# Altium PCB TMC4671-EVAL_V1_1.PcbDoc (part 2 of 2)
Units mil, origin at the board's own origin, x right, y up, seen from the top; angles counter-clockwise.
Board outline 2165.36 x 3346.46 mil, 6 copper layers (Top, GND1, MID, VM, GND2, Bottom), stack 61.733 mil thick; 157 components, 127 nets, 622 pads, 423 vias.
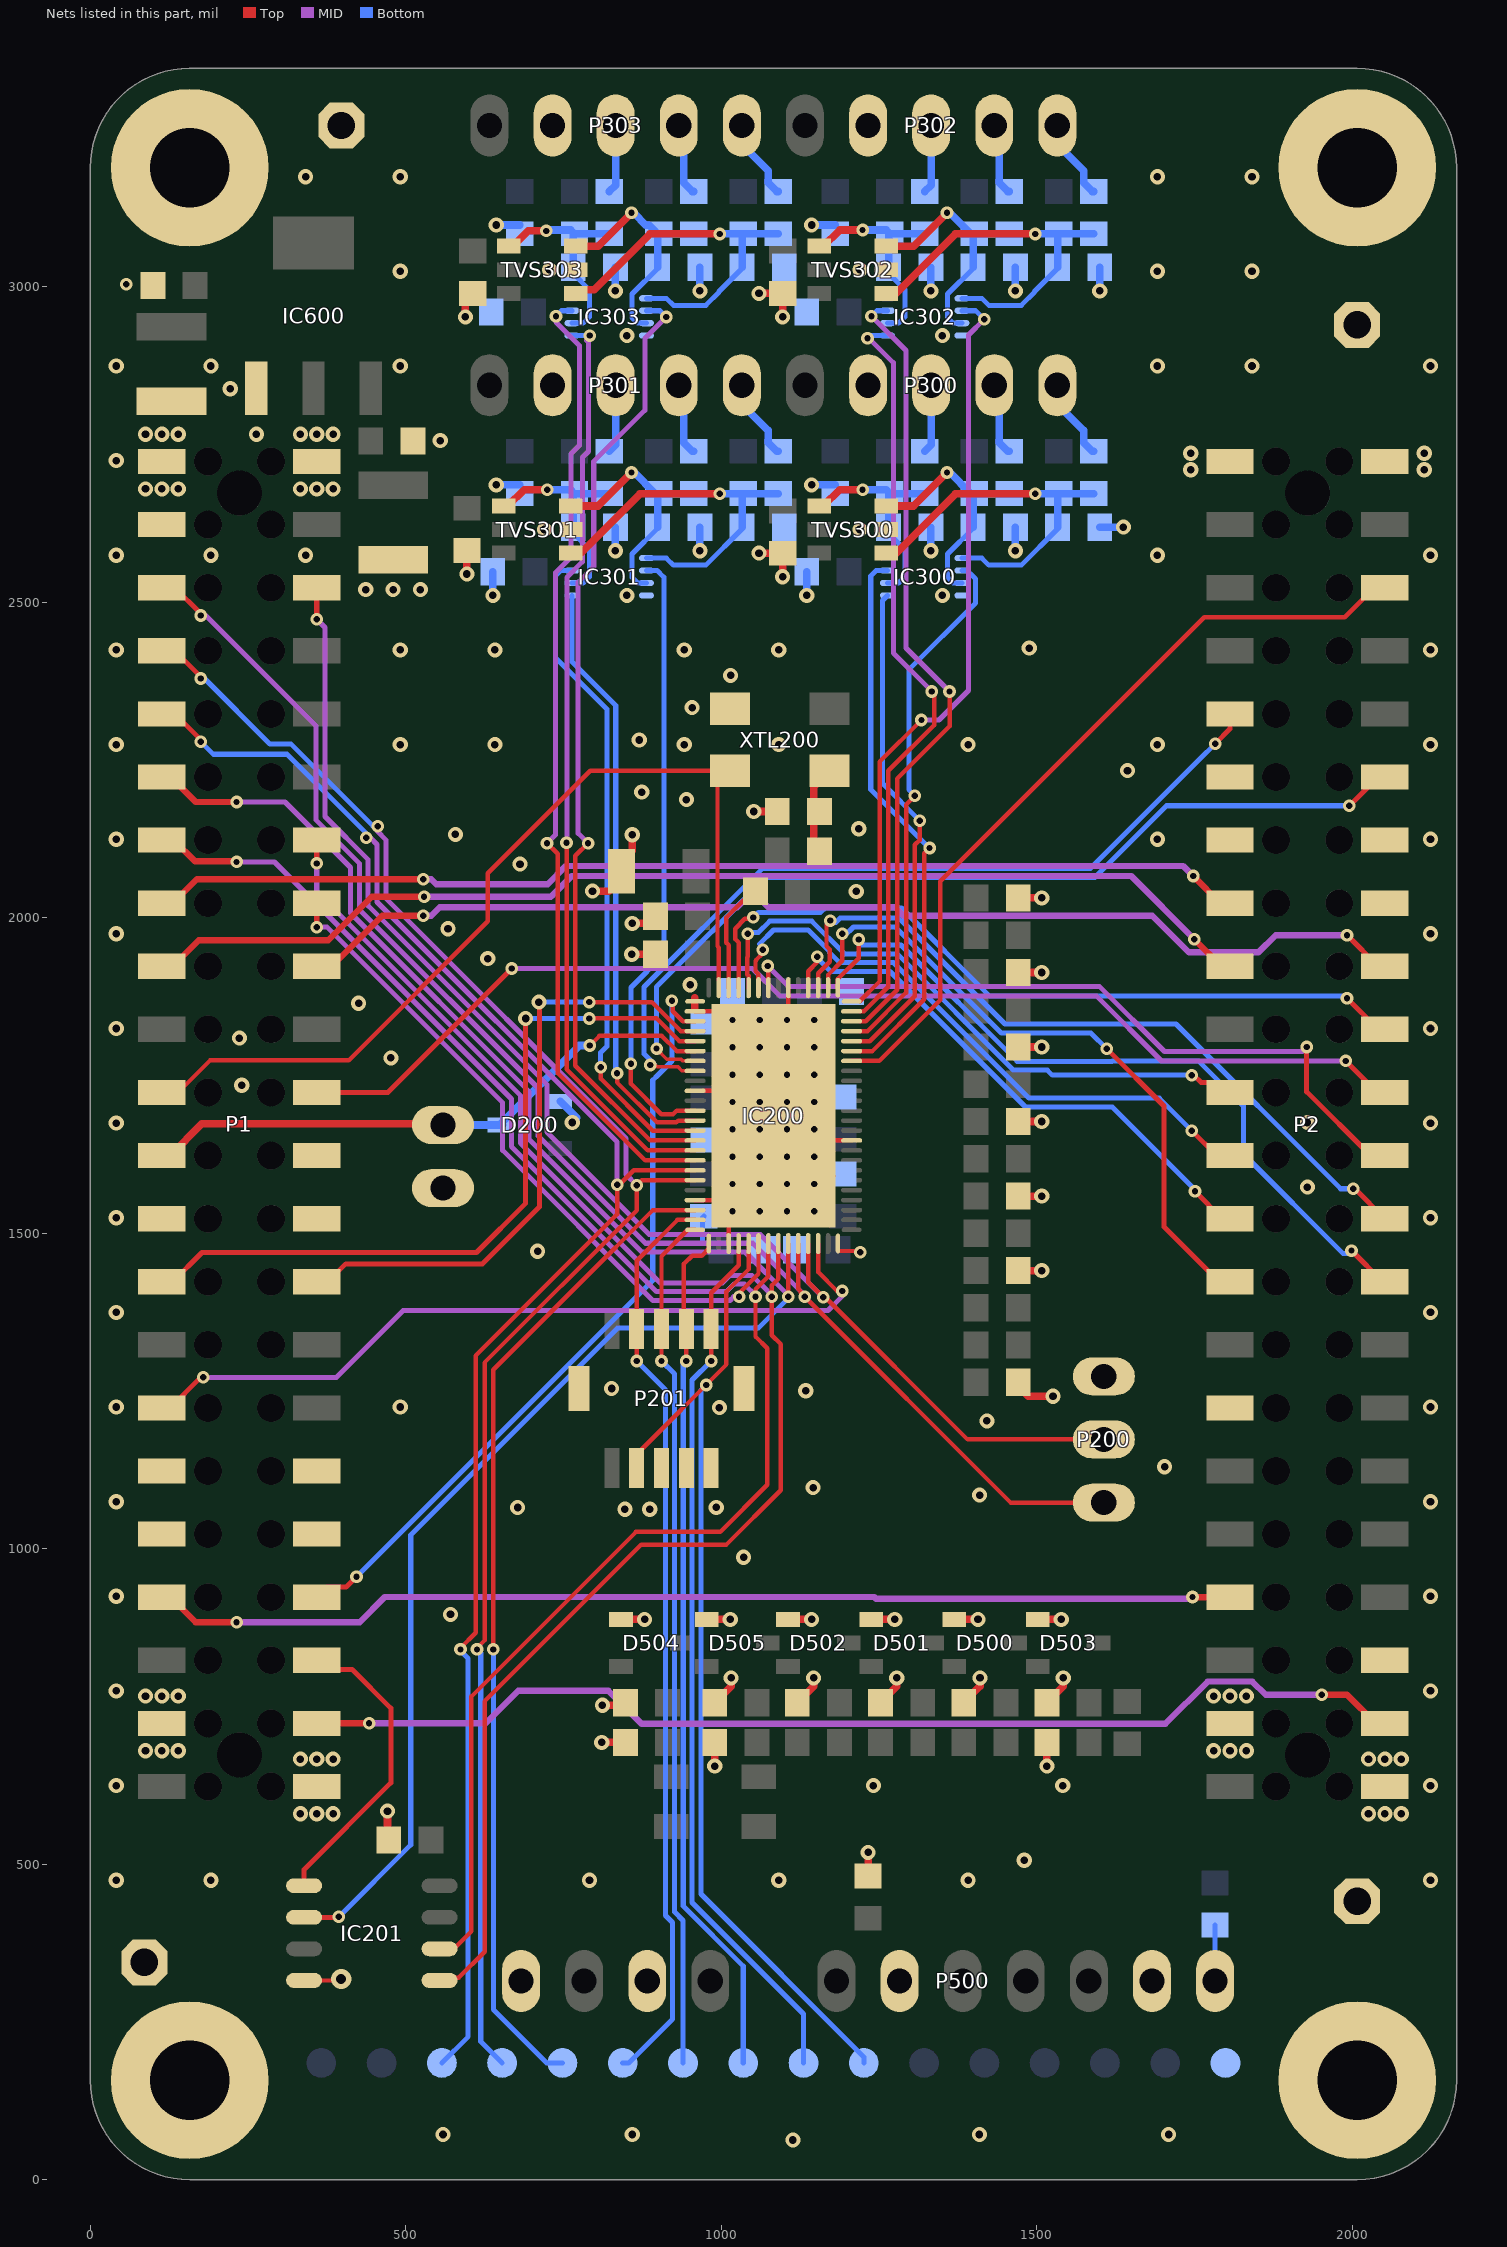
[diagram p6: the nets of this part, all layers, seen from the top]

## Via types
v1: diameter 24, hole 12, Top to Bottom, tented both sides, 171 vias
v2: diameter 20, hole 10, Top to Bottom, tented both sides, 136 vias
v3: diameter 24.1, hole 12, Top to Bottom, tented both sides, 67 vias
v4: diameter 24, hole 10, Top to Bottom, 32 vias
v5: diameter 26, hole 14, Top to Bottom, tented both sides, 7 vias
v6: diameter 32, hole 16, Top to Bottom, tented both sides, 6 vias
v7: diameter 39.37, hole 23.62, Top to Bottom, tented both sides, 2 vias
v8: diameter 50, hole 40, Top to Bottom, tented both sides, 2 vias

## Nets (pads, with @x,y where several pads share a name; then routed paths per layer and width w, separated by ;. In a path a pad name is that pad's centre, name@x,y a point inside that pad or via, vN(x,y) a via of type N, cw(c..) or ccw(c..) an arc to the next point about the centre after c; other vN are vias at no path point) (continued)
BRAKE_OUT: P400.2 R406.1 | length 88.6
  Bottom w8: P400.2@1782.68,314.96 R406.1@1782.68,403.6
CLK25: IC200.51 P1.23 XTL200.3 | length 1499.1
  Top w7.1: P1.23@113.5,1723.23 138.94,1723.23 189.73,1774.01 409.45,1774.01 629.92,1994.49 629.92,2070.52 792.53,2233.13 XTL200.3@986.5,2233.13 ; IC200.51@996.06,1901.99 996.06,1952.75 994.08,1954.74 994.08,2209.55 1001.53,2217 1002.62,2217 XTL200.3@986.5,2233.13 ; XTL200.3@1014.06,2233.13 XTL200.3@1013.82,2233.13 XTL200.3@986.5,2233.13
CS_CH0: IC201.1 P1.6 | length 487.1
  Top w8: IC201.1@339.01,465.94 339.01,491.76 476.38,629.13 476.38,747.24 414.97,808.65 373.52,808.65 P1.6@358.94,823.23
DBG_SPI_MISO: IC200.4 P201.9 TP9.1 | length 1402.5
  Top w7.1: v2(984.06,1297.62) P201.9@984.06,1348.47 984.06,1405.66 1027.56,1449.16 IC200.4@1027.56,1483.74
  Bottom w8: v2(984.06,1297.62) 953.76,1267.32 953.76,439.45 1130.45,262.77 TP9.1@1130.45,185.04
DBG_SPI_MOSI: IC200.1 P201.7 TP8.1 | length 1365.2
  Top w7.1: v2(944.69,1297.62) P201.7@944.69,1348.47 940.75,1352.41 940.75,1451.44 953.96,1464.65 969.38,1464.65 980.31,1475.59 IC200.1@980.31,1483.74
  Bottom w8: v2@939.76,1297.62 939.76,433.66 1034.91,338.51 TP8.1@1034.91,185.04
DBG_SPI_nSCS: IC200.75 P201.3 TP6.1 | length 1458.3
  Top w7.1: v2(865.95,1297.62) P201.3@865.95,1348.47 ; P201.3@869.95,1352.47 P201.3@865.95,1348.47 ; IC200.75@958.66,1521.15 930.55,1521.15 865.95,1456.55 P201.3@865.95,1348.47
  Bottom w8: TP6.1@843.83,185.04 853.26,185.04 922.68,254.45 922.68,407.79 911.76,418.71 911.76,1251.81 v2(865.95,1297.62)
DBG_SPI_SCK: IC200.76 P201.5 TP7.1 | length 1369
  Top w7.1: v2(905.32,1297.62) P201.5@905.32,1348.47 ; P201.5@909.32,1352.47 P201.5@905.32,1348.47 ; IC200.76@958.66,1505.4 947.13,1505.4 905.32,1463.59 P201.5@905.32,1348.47
  Bottom w8: v2(905.32,1297.62) 925.76,1277.18 925.76,424.5 939.37,410.9 TP7.1@939.37,185.04
DBG_SPI_TRG: IC200.5 P201.4 TP10.1 | length 1614.2
  Top w7.1: P201.4@865.95,1127.99 865.95,1149.73 1008.3,1292.08 1008.3,1407.73 1043.31,1442.74 IC200.5@1043.31,1483.74
  Bottom w8: v2(976.06,1259.65) 967.76,1251.36 967.76,452.71 1225.98,194.48 TP10.1@1225.98,185.04
DIO1: P1.9
DIO2: P1.10
DIO3: P1.11
DIO4: P1.12
DIO8: P1.19
DIO9: P1.20
DIO11: P1.22
DRV_ERROR: P2.13
EN_IN: IC200.55 P1.8 | length 1255.7
  Top w7.1: v2(921.85,1868.62) 923.12,1867.35 923.12,1851.98 938.99,1836.11 IC200.55@958.66,1836.11
  Top w8: P1.8@358.94,923.23 374.94,939.23 405.37,939.23 v2(421.85,955.7)
  Bottom w8: v2(421.85,955.7) 891.45,1425.31 891.45,1742.64 899.68,1750.87 921.85,1773.03 v2(921.85,1868.62)
EN_OUT: IC200.32 P2.40 | length 1266
  Top w7.1: IC200.32@1206.69,1773.11 1250.29,1773.11 1346.94,1869.76 1346.94,2057.76 1765.56,2476.38 1988.19,2476.38 2035.04,2523.23 P2.40@2051.85,2523.23
ENC1_A: IC200.35 IC300.2 | length 835.2
  Top w7.1: IC200.35@1219.43,1820.42 1231.82,1820.42 1292.94,1881.54 1292.94,2179.43 1306.85,2193.34 v2(1306.85,2193.62)
  Bottom w8: v2(1306.85,2193.62) 1297.3,2203.16 1297.3,2393.08 1403.31,2499.08 1403.31,2536.89 1394.57,2545.63 1393.65,2545.63 1388.88,2550.39 IC300.2@1381.5,2550.39
ENC1_A_5V: C308.2 IC300.6 R302.1 R312.1 TVS300.4 | length 355.3
  Top w12: TVS300.4@1155.12,2652.76 1162.01,2652.76 1187.59,2678.33 v2(1224.01,2678.33)
  Bottom w8: IC300.6@1263.39,2530.71 1281.1,2530.71 1290.94,2540.55 1290.94,2583.86 1265.35,2609.45 C308.2@1265.35,2619.29
  Bottom w12: v2(1224.01,2678.33) 1261.43,2678.33 R312.1@1267.32,2672.44 ; C308.2@1265.35,2619.29 1265.35,2670.47 R312.1@1267.32,2672.44 ; R302.1@1322.44,2672.44 R312.1@1267.32,2672.44
ENC1_A_IN: P300.3 R302.2 | length 109
  Bottom w12: R302.2@1322.44,2739.37 1332.68,2749.61 P300.3@1332.68,2844.09
ENC1_B: IC200.34 IC300.5 | length 783
  Top w7.1: IC200.34@1219.43,1804.61 1235.6,1804.61 1306.94,1875.95 1306.94,2115.7 1314.49,2123.25 v2(1314.49,2154.02)
  Bottom w8: IC300.5@1263.39,2511.02 1255.43,2503.07 1255.43,2213.08 v2(1314.49,2154.02)
ENC1_B_5V: C312.2 IC300.3 R301.1 R316.1 TVS300.3 | length 405.6
  Top w12: TVS300.3@1261.42,2652.76 1304.73,2652.76 v2(1357.87,2705.89)
  Bottom w8: IC300.3@1381.5,2530.71 1367.72,2530.71 1358.68,2539.74 1358.68,2576.8 C312.2@1399.21,2617.32
  Bottom w12: v2(1357.87,2705.89) 1361.8,2705.89 1395.26,2672.44 R316.1@1401.18,2672.44 ; C312.2@1399.21,2619.29 1399.21,2670.47 R316.1@1401.18,2672.44 ; R301.1@1456.3,2672.44 R316.1@1401.18,2672.44
ENC1_B_IN: P300.2 R301.2 | length 115.7
  Bottom w12: P300.2@1432.68,2844.09 1440.65,2836.13 1440.65,2753.06 1454.33,2739.37 R301.2@1456.3,2739.37
ENC1_N: IC200.33 IC300.7 | length 879.6
  Top w7.1: IC200.33@1219.43,1788.86 1239.65,1788.86 1321.85,1871.05 1321.85,2102.32 v2(1330.24,2110.72)
  Bottom w8: IC300.7@1263.39,2550.39 1245.67,2550.39 1236.98,2541.71 1236.98,2203.24 1329.51,2110.72 v2(1330.24,2110.72)
ENC1_N_5V: C316.2 IC300.1 R300.1 R320.1 TVS300.1 | length 604.3
  Top w12: TVS300.1@1261.42,2577.95 1277.17,2577.95 1371.31,2672.09 v2(1497.68,2672.09)
  Bottom w8: IC300.1@1381.5,2570.08 1413,2570.08 1424.18,2558.89 1475.67,2558.89 1533.07,2616.29 C316.2@1533.07,2619.29
  Bottom w12: v2(1497.68,2672.09) R320.1@1534.69,2672.09 ; C316.2@1533.07,2619.29 1533.07,2670.47 R320.1@1534.69,2672.09 ; R300.1@1590.16,2672.44 R320.1@1535.04,2672.44 R320.1@1534.69,2672.09
ENC1_N_IN: P300.1 R300.2 | length 129.7
  Bottom w12: P300.1@1532.68,2844.09 1532.68,2814.09 1574.41,2772.36 1574.41,2753.15 1588.19,2739.37 R300.2@1590.16,2739.37
ENC2_A: IC200.64 IC301.2 | length 980.4
  Top w7.1: v2(856.85,1768.62) 856.85,1736.98 905.06,1688.76 923.55,1688.76 929.16,1694.37 IC200.64@958.66,1694.37
  Bottom w8: v2(856.85,1768.62) 856.85,1889.52 908.98,1941.65 908.98,2539.85 898.43,2550.39 IC301.2@881.5,2550.39
ENC2_A_5V: C309.2 IC301.6 R305.1 R313.1 TVS301.4 | length 355.3
  Top w12: TVS301.4@655.12,2652.76 662.01,2652.76 687.59,2678.33 v2(724.01,2678.33)
  Bottom w8: IC301.6@763.39,2530.71 781.1,2530.71 790.94,2540.55 790.94,2583.86 765.35,2609.45 C309.2@765.35,2619.29
  Bottom w12: v2(724.01,2678.33) 761.43,2678.33 R313.1@767.32,2672.44 ; C309.2@765.35,2619.29 765.35,2670.47 R313.1@767.32,2672.44 ; R305.1@822.44,2672.44 R313.1@767.32,2672.44
ENC2_A_IN: P301.3 R305.2 | length 109
  Bottom w12: R305.2@822.44,2739.37 832.68,2749.61 P301.3@832.68,2844.09
ENC2_B: IC200.65 IC301.5 | length 952.8
  Top w7.1: v2(834.94,1753.76) 834.94,1739.08 898.36,1675.66 928.97,1675.66 931.93,1678.61 IC200.65@958.66,1678.63
  Bottom w8: IC301.5@763.39,2511.02 763.39,2405.88 832.85,2336.42 832.85,1755.85 v2(834.94,1753.76)
ENC2_B_5V: C313.2 IC301.3 R304.1 R317.1 TVS301.3 | length 405.6
  Top w12: TVS301.3@761.42,2652.76 804.73,2652.76 v2(857.87,2705.89)
  Bottom w8: IC301.3@881.5,2530.71 867.72,2530.71 858.68,2539.74 858.68,2576.8 C313.2@899.21,2617.32
  Bottom w12: v2(857.87,2705.89) 861.8,2705.89 895.26,2672.44 R317.1@901.18,2672.44 ; C313.2@899.21,2619.29 899.21,2670.47 R317.1@901.18,2672.44 ; R304.1@956.3,2672.44 R317.1@901.18,2672.44
ENC2_B_IN: P301.2 R304.2 | length 115.7
  Bottom w12: P301.2@932.68,2844.09 940.65,2836.13 940.65,2753.06 954.33,2739.37 R304.2@956.3,2739.37
ENC2_N: IC200.66 IC301.7 | length 1048.6
  Top w7.1: v2(808.94,1763.23) 808.94,1745.28 891.66,1662.56 934.4,1662.56 934.65,1662.82 IC200.66@958.66,1662.88 IC200.66@958.66,1662.88
  Bottom w8: IC301.7@763.39,2550.39 745.67,2550.39 736.98,2541.71 736.98,2412.48 818.85,2330.62 818.85,1796.34 808.94,1786.43 v2(808.94,1763.23)
ENC2_N_5V: C317.2 IC301.1 R303.1 R321.1 TVS301.1 | length 604.3
  Top w12: TVS301.1@761.42,2577.95 777.17,2577.95 871.31,2672.09 v2(997.68,2672.09)
  Bottom w8: IC301.1@881.5,2570.08 913,2570.08 924.18,2558.89 975.67,2558.89 1033.07,2616.29 C317.2@1033.07,2619.29
  Bottom w12: v2(997.68,2672.09) R321.1@1034.69,2672.09 ; C317.2@1033.07,2619.29 1033.07,2670.47 R321.1@1034.69,2672.09 ; R303.1@1090.16,2672.44 R321.1@1035.04,2672.44 R321.1@1034.69,2672.09
ENC2_N_IN: P301.1 R303.2 | length 129.7
  Bottom w12: P301.1@1032.68,2844.09 1032.68,2814.09 1074.41,2772.36 1074.41,2753.15 1088.19,2739.37 R303.2@1090.16,2739.37
EXT_REF: P2.6
GND: C200.2 C201.1 C300.1 C301.1 C302.1 C303.1 C304.2 C305.2 C306.2 C307.2 C308.1 C309.1 C310.1 C311.1 C312.1 C313.1 C314.1 C315.1 C316.1 C317.1 C318.1 C319.1 C320.1 C321.1 C322.1 C323.1 C500.1 C501.1 C502.1 C503.1 C504.1 C505.1 C506.1 C507.1 C508.1 C600.1 C601.1 C602.1 C603.1 C604.1 C605.1 C606.1 C607.1 C608.1 C609.1 C610.1 C611.1 C612.1 C613.1 C614.2 C615.1 D200.1 D500.1 D501.1 D502.1 D503.1 D504.1 D505.1 IC200.3 IC200.14 IC200.24 IC200.44 IC200.53 IC200.54 IC200.62 IC200.73 IC200.77 IC201.4 IC300.4 IC301.4 IC302.4 IC303.4 IC600.1 MNT1.1 MNT2.1 MNT3.1 MNT4.1 P1.2 P1.3 P1.43 P1.44 P2.2 P2.3 P2.43 P2.44 P200.1 P201.6 P201.8 P201.10 P201.11 P201.12 P202.2 P300.4 P301.4 P302.4 P303.4 P400.1 P500.4 P501.2 P502.2 PIN1.1 PIN2.1 PIN3.1 PIN4.1 R401.1 R403.1 R405.1 R408.1 R410.1 R507.2 R508.2 R509.2 TP14.1 TVS300.2 TVS301.2 TVS302.2 TVS303.2 XTL200.2 | length 3304.7
  Top w6: IC201.4@339.01,315.94 395.47,315.94 v6(397.64,318.11) ; IC200.77@988.25,1851.85 1082.68,1757.43 IC200.77@1082.68,1686.5 1122.05,1647.13 IC200.77@1178.1,1591.08 ; IC200.14@1185.04,1483.74 1185.04,1472.04 1220.57,1472.04 v2(1220.57,1470) v2@1220,1470
  Top w7.1: IC200.73@958.66,1552.64 IC200.77@988.25,1552.64 ; IC200.54@958.66,1851.85 IC200.77@988.25,1851.85 ; IC200.62@971.39,1725.87 IC200.77@1043.31,1725.87 ; IC200.3@1011.81,1483.74 IC200.77@1011.81,1615.63 ; IC200.77@1106.3,1710.12 IC200.44@1106.3,1889.26 ; IC200.77@1122.05,1647.13 IC200.24@1206.69,1647.13
  Top w8: IC200.77@988.25,1552.64 1011.81,1576.2 IC200.77@1011.81,1584.14 ; IC200.77@1011.81,1615.63 v4(1017.72,1621.54) v4(1061.02,1664.85) IC200.77@1082.68,1686.5 ; IC200.77@1043.31,1725.87 IC200.77@1082.68,1686.5 ; v4(1104.33,1708.15) IC200.77@1082.68,1686.5
  Top w11.81: IC200.54@957.8,1855.21 957.8,1873.2
  Top w12: v1(471.08,584.11) 471.08,540.32 C201.1@473.05,538.36 ; v1(594.49,2952.36) C307.2@594.49,2989.76 ; v1(596.94,2544.9) C305.2@596.94,2582.3 ; v1(795.95,2042.41) C612.1@821.5,2042.41 ; v1(810.63,693.04) R507.2@848.03,693.04 ; v1(811.7,751.97) 843.97,751.97 C506.1@848.03,756.03 ; D504.1@841.14,888.09 v1(878.54,888.09) ; v1(858.24,1942.37) C613.1@895.64,1942.37 ; v1(858.94,1991.23) 884.49,1991.23 C614.2@895.64,2002.37 ; C612.1@858.95,2106.06 v1(858.95,2131.61) ; D505.1@976.97,888.09 v1(1014.37,888.09) ; v1(989.76,655.64) R508.2@989.76,693.04 ; C507.1@989.76,756.03 1015.55,781.82 v1(1015.55,795.28) ; v1(1051.46,2168.52) C200.2@1088.86,2168.52 ; v1(1059.84,2577.95) C304.2@1097.24,2577.95 v1(1097.24,2540.55) ; v1(1059.84,2989.76) C306.2@1097.24,2989.76 v1(1097.24,2952.36) ; D502.1@1105.79,888.09 v1(1143.19,888.09) ; C505.1@1120.55,756.03 1146.34,781.82 v1(1146.34,795.28) ; C500.1@1232.68,481.42 v1(1232.68,518.83) ; D501.1@1237.68,888.09 v1(1275.08,888.09) ; C504.1@1252.44,756.03 1278.23,781.82 v1(1278.23,795.28) ; D500.1@1369.57,888.09 v1(1406.97,888.09) ; C503.1@1384.33,756.03 1410.12,781.82 v1(1410.12,795.28) ; C501.1@1470.63,1263.78 1467.47,1260.62 1486.47,1241.62 v1(1525.85,1241.62) ; R410.1@1470.63,1440.95 v1(1508.03,1440.95) ; C502.1@1470.63,1559.06 v1(1508.03,1559.06) ; R408.1@1470.63,1677.16 v1(1508.03,1677.16) ; R405.1@1470.63,1795.28 v1(1508.03,1795.28) ; R403.1@1470.63,1913.39 v1(1508.03,1913.39) ; R401.1@1470.63,2031.49 v1(1508.03,2031.49) ; D503.1@1501.46,888.09 v1(1538.86,888.09) ; v1(1516.22,655.64) R509.2@1516.22,693.04 ; C508.1@1516.22,756.03 1542.01,781.82 v1(1542.01,795.28)
  Bottom w8: 970,1485 970,1524.61 C610.1@972.44,1527.05
  Bottom w12: v1(637.99,2511.02) C321.1@637.99,2548.43 ; v1(643.31,2686.22) C301.1@680.71,2686.22 ; v1(643.31,3098.03) C303.1@680.71,3098.03 ; D200.1@745.08,1709.05 770.67,1683.46 763.78,1676.57 v1(763.78,1675.59) ; v1(832.28,2581.89) C309.1@832.28,2619.29 ; v1(832.28,2993.7) C311.1@832.28,3031.1 ; v1(966.14,2581.89) C313.1@966.14,2619.29 ; v1(966.14,2993.7) C315.1@966.14,3031.1 ; v1(1135.43,2511.02) C320.1@1135.43,2548.43 ; v1(1143.31,2686.22) C300.1@1180.71,2686.22 ; v1(1143.31,3098.03) C302.1@1180.71,3098.03 ; v1(1332.28,2581.89) C308.1@1332.28,2619.29 ; v1(1332.28,2993.7) C310.1@1332.28,3031.1 ; v1(1466.14,2581.89) C312.1@1466.14,2619.29 ; v1(1466.14,2993.7) C314.1@1466.14,3031.1 ; C316.1@1600,2619.29 v1(1637.4,2619.29) ; v1(1600,2993.7) C318.1@1600,3031.1
  other v1: 559.06,71.65 859.06,71.65 1409.06,71.65 1709.06,71.65 1480.31,506.3 332.96,579.92 358.94,579.92 384.92,579.92 2025.87,579.92 2051.85,579.92 2077.84,579.92 332.96,666.54 358.94,666.54 384.92,666.54 2025.87,666.54 2051.85,666.54 2077.84,666.54 87.52,679.92 113.5,679.92 139.48,679.92 1780.43,679.92 1806.41,679.92 1832.4,679.92 87.52,766.54 113.5,766.54 139.48,766.54 1780.43,766.54 1806.41,766.54 1832.4,766.54 570.87,896.06 1035.43,986.61 847.39,1062.62 886.76,1062.62 677.17,1065.35 992.06,1065.65 1409.45,1085.04 1145.67,1096.85 1421.06,1202.65 997.06,1223.65 1133.86,1250.39 826.23,1253.98 709.06,1471.65 1929.13,1573.23 1929.13,1675.59 240.16,1734.64 476.38,1777.95 236.22,1809.45 425.2,1864.57 950.63,1893.89 629.92,1935.43 566.93,1982.68 1213.94,2041.89 681.1,2085.04 578.74,2132.28 1217.94,2141.23 944.88,2187.4 874.02,2199.21 1643.94,2233.23 870.08,2281.89 953.94,2333.23 1014.94,2384.23 1488.19,2427.56 850.5,2510.96 1350.5,2510.96 436.54,2520.16 479.84,2520.16 523.15,2520.16 719.76,2615.42 1219.76,2615.42 87.52,2679.92 113.5,2679.92 139.48,2679.92 332.96,2679.92 358.94,2679.92 384.92,2679.92 1744.09,2710.24 2114.17,2710.24 1744.09,2736.22 2114.17,2736.22 554.65,2756.38 87.52,2766.54 113.5,2766.54 139.48,2766.54 263.31,2766.54 332.96,2766.54 358.94,2766.54 384.92,2766.54 221.85,2838.62 850.5,2922.77 1350.5,2922.77 727.63,3027.23 1219.76,3027.23
  other v2: 56.94,3004.23
  other v3: 1113.68,62.96 41.23,474.64 191.23,474.64 791.23,474.64 1091.23,474.64 1391.23,474.64 2124.12,474.64 41.23,624.64 1241.23,624.64 1541.23,624.64 2124.12,624.64 41.23,774.64 2124.12,774.64 41.23,924.64 2124.12,924.64 41.23,1074.64 2124.12,1074.64 1702.68,1129.96 41.23,1224.64 491.23,1224.64 2124.12,1224.64 41.23,1374.64 2124.12,1374.64 41.23,1524.64 2124.12,1524.64 41.23,1674.64 2124.12,1674.64 41.23,1824.64 2124.12,1824.64 41.23,1974.64 2124.12,1974.64 41.23,2124.64 1691.23,2124.64 2124.12,2124.64 41.23,2274.64 491.23,2274.64 641.23,2274.64 941.23,2274.64 1091.23,2274.64 1391.23,2274.64 1691.23,2274.64 2124.12,2274.64 41.23,2424.64 491.23,2424.64 641.23,2424.64 941.23,2424.64 1091.23,2424.64 2124.12,2424.64 41.23,2574.64 191.23,2574.64 341.23,2574.64 1691.23,2574.64 2124.12,2574.64 41.23,2724.64 41.23,2874.64 191.23,2874.64 491.23,2874.64 1691.23,2874.64 1841.23,2874.64 2124.12,2874.64 491.23,3024.64 1691.23,3024.64 1841.23,3024.64 341.23,3174.64 491.23,3174.64 1691.23,3174.64 1841.23,3174.64
  other v4: 1017.72,1534.93 1061.02,1534.93 1104.33,1534.93 1147.64,1534.93 1017.72,1578.23 1061.02,1578.23 1104.33,1578.23 1147.64,1578.23 1061.02,1621.54 1104.33,1621.54 1147.64,1621.54 1017.72,1664.85 1104.33,1664.85 1147.64,1664.85 1017.72,1708.15 1061.02,1708.15 1147.64,1708.15 1017.72,1751.46 1061.02,1751.46 1104.33,1751.46 1147.64,1751.46 1017.72,1794.77 1061.02,1794.77 1104.33,1794.77 1147.64,1794.77 1017.72,1838.08 1061.02,1838.08 1104.33,1838.08 1147.64,1838.08
GPIO0: IC200.70 P1.35 TP3.1 | length 2779.4
  Top w7.1: v2(586.85,840.46) 586.85,842.74 610.85,866.74 610.85,1306.26 835.07,1530.48 v2(835.07,1577.16) 838.59,1577.16 861.31,1599.89 IC200.70@958.66,1599.89
  Top w8: P1.35@113.5,2323.23 133.94,2323.23 174.94,2282.23 v2(174.94,2279.23)
  MID w8: v2(437.16,2126.76) 443.95,2126.76 454.5,2116.2 454.5,2025.1 835.07,1644.53 v2(835.07,1577.16)
  Bottom w8: v2(174.94,2279.23) 194.94,2259.23 311.76,2259.23 437.16,2133.83 v2(437.16,2126.76) ; TP3.1@557.22,185.04 598.85,226.67 598.85,826.11 ; v2(586.85,840.46) 586.85,838.17 598.85,826.17
GPIO1: IC200.71 P1.37 TP4.1 | length 2806.4
  Top w7.1: v2(612.85,840.46) 612.85,842.74 624.85,854.74 624.85,1295.13 865.94,1536.23 v2(865.94,1576.23) 873.85,1584.14 IC200.71@958.66,1584.14
  Top w8: P1.37@113.5,2423.23 133.94,2423.23 174.94,2382.23 v2(174.94,2379.23)
  MID w8: v2(455.54,2145.14) 455.54,2136.66 468.5,2123.7 468.5,2030.9 849.07,1650.33 849.07,1593.1 v2(865.94,1576.23)
  Bottom w8: v2(174.94,2379.23) 180.94,2379.23 284.94,2275.23 318.39,2275.23 448.47,2145.14 v2(455.54,2145.14) ; v2(612.85,840.46) 618.85,834.46 618.85,218.95 TP4.1@652.76,185.04
GPIO2: IC200.74 TP5.1 | length 1583.4
  Top w7.1: v2(638.85,840.46) 638.85,1283.91 775.56,1420.62 891.83,1536.89 IC200.74@958.66,1536.89
  Bottom w8: v2(638.85,840.46) 638.85,269.62 723.43,185.04 TP5.1@748.29,185.04
GPIO3: P1.41
HALL_UX: IC200.38 IC302.2 | length 1220
  Top w7.1: IC200.38@1219.43,1867.67 1250.94,1899.18 1250.94,2247.26 v2(1317.3,2313.62)
  MID w8: v2(1317.3,2313.62) 1345.13,2313.62 1391.85,2360.34 1391.85,2923.62 v2(1416.85,2948.62)
  Bottom w8: IC302.2@1381.5,2962.21 1403.26,2962.21 v2(1416.85,2948.62)
HALL_UX_5V: C310.2 IC302.6 R308.1 R314.1 TVS302.4 | length 355.3
  Top w12: TVS302.4@1155.12,3064.57 1162.01,3064.57 1187.59,3090.14 v2(1224.01,3090.14)
  Bottom w8: IC302.6@1263.39,2942.52 1281.1,2942.52 1290.94,2952.36 1290.94,2995.67 1265.35,3021.26 C310.2@1265.35,3031.1
  Bottom w12: v2(1224.01,3090.14) 1261.43,3090.14 R314.1@1267.32,3084.25 ; C310.2@1265.35,3031.1 1265.35,3082.28 R314.1@1267.32,3084.25 ; R308.1@1322.44,3084.25 R314.1@1267.32,3084.25
HALL_UX_IN: P302.3 R308.2 | length 109
  Bottom w12: R308.2@1322.44,3151.18 1332.68,3161.42 P302.3@1332.68,3255.91
HALL_V: IC200.37 IC302.5 | length 1206
  Top w7.1: IC200.37@1219.43,1851.92 1226.27,1851.92 1264.94,1890.59 1264.94,2232.97 1337.3,2305.34 1337.3,2354.88 v2(1333.56,2358.62)
  MID w8: v2(1231.85,2918.62) 1233.93,2918.62 1272.68,2879.88 1272.68,2419.84 1329.66,2362.86 1337.8,2362.86 v2(1333.56,2358.62)
  Bottom w8: v2(1231.85,2918.62) 1236.06,2922.84 IC302.5@1263.39,2922.84
HALL_V_5V: C314.2 IC302.3 R307.1 R318.1 TVS302.3 | length 405.6
  Top w12: TVS302.3@1261.42,3064.57 1304.73,3064.57 v2(1357.87,3117.7)
  Bottom w8: IC302.3@1381.5,2942.52 1367.72,2942.52 1358.68,2951.55 1358.68,2988.61 C314.2@1399.21,3029.13
  Bottom w12: v2(1357.87,3117.7) 1361.8,3117.7 1395.26,3084.25 R318.1@1401.18,3084.25 ; C314.2@1399.21,3031.1 1399.21,3082.28 R318.1@1401.18,3084.25 ; R307.1@1456.3,3084.25 R318.1@1401.18,3084.25
HALL_V_IN: P302.2 R307.2 | length 115.7
  Bottom w12: P302.2@1432.68,3255.91 1440.65,3247.94 1440.65,3164.87 1454.33,3151.18 R307.2@1456.3,3151.18
HALL_WY: IC200.36 IC302.7 | length 1262.3
  Top w7.1: IC200.36@1219.43,1836.17 1229.05,1836.17 1278.94,1886.06 1278.94,2220.72 1361.85,2303.62 v2(1361.85,2358.62)
  MID w8: v2(1238.05,2953.66) 1292.68,2899.03 1292.68,2427.79 v2(1361.85,2358.62)
  Bottom w8: v2(1238.05,2953.66) 1246.6,2962.21 IC302.7@1263.39,2962.21
HALL_WY_5V: C318.2 IC302.1 R306.1 R322.1 TVS302.1 | length 604.3
  Top w12: TVS302.1@1261.42,2989.76 1277.17,2989.76 1371.31,3083.91 v2(1497.68,3083.91)
  Bottom w8: IC302.1@1381.5,2981.89 1413,2981.89 1424.18,2970.7 1475.67,2970.7 1496.53,2991.56 1496.53,2992.59 1533.07,3029.13 C318.2@1533.07,3031.1
  Bottom w12: v2(1497.68,3083.91) R322.1@1534.69,3083.91 ; C318.2@1533.07,3031.1 1533.07,3082.28 R322.1@1534.69,3083.91 ; R306.1@1590.16,3084.25 R322.1@1535.04,3084.25 R322.1@1534.69,3083.91
HALL_WY_IN: P302.1 R306.2 | length 129.7
  Bottom w12: P302.1@1532.68,3255.91 1532.68,3225.91 1574.41,3184.17 1574.41,3164.96 1588.19,3151.18 R306.2@1590.16,3151.18
ID_CH1: P1.7 P2.7 | length 1728.5
  Top w10: P1.7@113.5,923.23 127.24,923.23 166.85,883.62 v2(231.85,883.62) ; v2(1746.85,923.62) 1747.24,923.23 P2.7@1806.41,923.23
  MID w10: v2(231.85,883.62) 426.85,883.62 466.85,923.62 1242.39,923.62 1245.36,920.65 1743.88,920.65 v2(1746.85,923.62)
ID_CLK: P1.4 P2.4 | length 1791.2
  Top w10: P1.4@358.94,723.23 441.45,723.23 v2(441.85,723.62) ; v2(1951.85,768.62) 1991.85,768.62 2037.24,723.23 P2.4@2051.85,723.23
  MID w10: v2(441.85,723.62) 627.01,723.62 678.36,774.97 821.22,774.97 873.57,722.62 1703.99,722.62 1770.9,789.54 1841.92,789.54 1862.84,768.62 v2(1951.85,768.62)
NetC200_1: C200.1 L200.2 XTL200.4 | length 138
  Top w12: L200.2@1146.3,2105.53 1146.3,2207.89 XTL200.4@1171.54,2233.13
nRST: IC200.50 R200.1 | length 159.4
  Top w7.1: IC200.50@1011.81,1889.26 1011.81,1956.8 1008.08,1960.54 1008.08,2000.6 R200.1@1040.94,2033.46
PWM_H_IDLE: IC200.59 P2.34 | length 1459.8
  Top w6: v2(897.54,1792.79) 897.54,1792.12 897.63,1792.02 897.5,1791.89 913.53,1775.86 936.24,1775.86 938.62,1773.47 958.3,1773.47 IC200.59@958.66,1773.11
  Top w8: v2(1995.59,2177.64) 2041.18,2223.23 P2.34@2051.85,2223.23
  Bottom w8: v2(897.54,1792.79) 897.54,1890.61 1070.81,2063.89 1592.03,2063.89 1705.78,2177.64 v2(1995.59,2177.64)
PWM_IN: D200.3 IC200.58 P1.21 P202.1 | length 942.1
  Top w7.1: v2(791.85,1797.62) 807.02,1812.79 905.82,1812.79 929.75,1788.86 IC200.58@958.66,1788.86
  Top w12: P1.21@113.5,1623.23 126.45,1623.23 176.85,1673.62 557.09,1673.62 P202.1@559.06,1671.65
  Bottom w8: D200.3@648.62,1671.65 D200.3@655.51,1671.65
  Bottom w12: P202.1@559.06,1671.65 D200.3@648.62,1671.65 774.59,1797.62 v2(791.85,1797.62)
PWM_L_IDLE: IC200.60 P2.35 | length 1341.3
  Top w6: v2(887.32,1766.79) 888.9,1768.37 888.9,1773.62 898.66,1763.86 931.26,1763.86 937.4,1757.72 958.3,1757.72 IC200.60@958.66,1757.37
  Top w8: v2(1782.99,2276.07) 1806.41,2299.49 P2.35@1806.41,2323.23
  Bottom w8: v2(887.32,1766.79) 891.67,1766.79 893.46,1768.59 877.54,1784.51 877.54,1890.41 1065.6,2078.47 1585.39,2078.47 1758.62,2251.7 v2(1782.99,2276.07)
PWM_UX1_H: IC200.39 P2.18 | length 1202.5
  Top w7.1: IC200.39@1185.04,1889.26 1185.04,1903.33 1217.85,1936.13 v2(1217.85,1965.62)
  Top w8: v2(1998.85,1472.62) 2048.24,1423.23 P2.18@2051.85,1423.23
  Bottom w8: v2(1217.85,1965.62) 1217.85,1957.62 1218.46,1957 1284.77,1957 1469.15,1772.62 1619.13,1772.62 1619.78,1773.28 1756.19,1773.28 1827.85,1701.62 1827.85,1625.62 1985.85,1467.62 1993.85,1467.62 v2(1998.85,1472.62)
PWM_UX1_L: IC200.40 P2.17 | length 1064.1
  Top w7.1: IC200.40@1169.29,1889.26 1169.29,1909.41 1191.85,1931.96 v2(1191.85,1974.69)
  Top w8: v2(1610.85,1792.62) 1701.85,1701.62 1701.85,1510.3 1788.91,1423.23 P2.17@1806.41,1423.23
  Bottom w8: v2(1191.85,1974.69) 1191.85,1971.62 1192.85,1970.62 1194.56,1970.62 1209.56,1985.62 1275.95,1985.62 1443.95,1817.62 1585.85,1817.62 v2(1610.85,1792.62)
PWM_VX2_H: IC200.41 P2.20 | length 1199.1
  Top w7.1: IC200.41@1153.54,1889.26 1153.54,1912.18 1171.94,1930.58 1171.94,1949.81 1166.85,1954.91 1166.85,1989.62 v2(1172.85,1995.62)
  Top w8: v2(2001.85,1570.62) 2004.46,1570.62 P2.20@2051.85,1523.23
  Bottom w8: v2(1172.85,1995.62) 1175.85,1992.62 1181.49,1992.62 1188.49,1999.62 1281.75,1999.62 1449.75,1831.62 1720.85,1831.62 1981.85,1570.62 v2(2001.85,1570.62)
PWM_VX2_L: IC200.42 P2.19 | length 884
  Top w7.1: IC200.42@1137.8,1889.26 1137.8,1915.48 1152.3,1929.99 1152.3,1937.87 v2(1151.94,1938.23)
  Top w8: v2(1750.85,1566.62) 1794.24,1523.23 P2.19@1806.41,1523.23
  Bottom w8: v2(1151.94,1938.23) 1151.94,1936.56 1173.49,1915 1267.37,1915 1482.15,1700.22 1619.85,1700.22 1750.85,1569.22 v2(1750.85,1566.62)
PWM_WY1_H: IC200.46 P2.22 | length 1184.6
  Top w7.1: v2(1073.85,1923.62) 1073.85,1915.15 1074.8,1914.2 IC200.46@1074.8,1889.26
  Top w8: v2(1927.94,1795.23) 1927.94,1724.23 2028.94,1623.23 P2.22@2051.85,1623.23
  MID w8: v2(1073.85,1923.62) 1106.08,1891.39 1599.3,1891.39 1702.46,1788.23 1920.94,1788.23 v2(1927.94,1795.23)
PWM_WY1_L: IC200.47 P2.21 | length 982.1
  Top w7.1: IC200.47@1059.06,1889.26 1058.99,1889.32 1058.99,1910.83 1054.3,1915.52 1054.3,1931.72 1055.18,1932.6 1055.18,1933.24 1066.02,1944.09 v2(1066.02,1949.62)
  Top w8: v2(1745.85,1662.62) 1785.24,1623.23 P2.21@1806.41,1623.23
  Bottom w8: v2(1066.02,1949.62) 1066.02,1953.56 1060.85,1958.73 1082.73,1980.62 1137.83,1980.62 1171.94,1946.51 1171.94,1944.84 1187.78,1929 1273.17,1929 1487.95,1714.22 1694.25,1714.22 v2(1745.85,1662.62)
PWM_Y2_H: IC200.48 P2.23 | length 971.6
  Top w7.1: v2(1042.08,1974.62) 1042.08,1938.03 1041.2,1937.15 1041.2,1910.1 1043.31,1907.99 IC200.48@1043.31,1889.26
  Top w8: v2(1745.85,1750.62) 1749.09,1750.62 1760.49,1739.23 1790.41,1739.23 P2.23@1806.41,1723.23
  Bottom w8: v2(1042.08,1974.62) 1044.37,1976.92 1059.23,1976.92 1076.93,1994.62 1143.63,1994.62 1195.25,1943 1278.97,1943 1463.35,1758.62 1516.74,1758.62 1524.74,1750.62 v2(1745.85,1750.62)
PWM_Y2_L: IC200.49 P2.26 | length 1218.9
  Top w7.1: IC200.49@1027.56,1889.26 1027.56,1960.85 1022.08,1966.34 1022.08,1982.91 1037.5,1998.33 1048.55,1998.33 v2(1050.85,2000.62)
  Top w8: v2(1991.85,1872.62) 2041.24,1823.23 P2.26@2051.85,1823.23
  Bottom w8: v2(1050.85,2000.62) 1058.85,2008.62 1157.56,2008.62 1164.56,2015.62 1285.55,2015.62 1424.84,1876.33 1988.14,1876.33 v2(1991.85,1872.62)
REF_H: IC200.68 IC303.5 | length 1465.8
  Top w7.1: v2(754.85,2119.23) 754.85,1759.78 883.31,1631.31 IC200.68@958.66,1631.38 IC200.68@958.66,1631.38
  MID w8: v2(754.85,2119.23) 755.23,2119.61 755.23,2539.47 779.94,2564.18 779.94,2729.67 789.5,2739.23 789.5,2912.47 786.68,2915.29 786.68,2917.97 v2(791.55,2922.84)
  Bottom w8: IC303.5@763.39,2922.84 v2(791.55,2922.84)
REF_H_5V: C311.2 IC303.6 R311.1 R315.1 TVS303.4 | length 347.4
  Top w12: TVS303.4@662.99,3064.57 669.88,3064.57 694.01,3088.7 v2(722.56,3088.7)
  Bottom w8: IC303.6@763.39,2942.52 781.1,2942.52 790.94,2952.36 790.94,2995.67 765.35,3021.26 C311.2@765.35,3031.1
  Bottom w12: v2(722.56,3088.7) 724.01,3090.14 761.43,3090.14 R315.1@767.32,3084.25 ; C311.2@765.35,3031.1 765.35,3082.28 R315.1@767.32,3084.25 ; R311.1@822.44,3084.25 R315.1@767.32,3084.25
REF_H_IN: P303.2 R310.2 | length 115.7
  Bottom w12: P303.2@932.68,3255.91 940.65,3247.94 940.65,3164.87 954.33,3151.18 R310.2@956.3,3151.18
REF_L: IC200.67 IC303.2 | length 1533.8
  Top w7.1: v2(788.94,2118.32) 768.85,2098.23 768.85,1765.58 887.29,1647.13 IC200.67@958.66,1647.13
  MID w8: v2(788.94,2118.32) 773.23,2134.03 773.23,2532.02 797.94,2556.73 797.94,2723.47 878.94,2804.47 878.94,2918.23 v2(912.94,2952.23)
  Bottom w8: IC303.2@881.5,2962.21 902.96,2962.21 v2(912.94,2952.23)
REF_L_5V: C315.2 IC303.3 R310.1 R319.1 TVS303.3 | length 397.7
  Top w12: TVS303.3@769.29,3064.57 804.73,3064.57 v2(857.87,3117.7) v2@861.8,3116.66
  Bottom w8: IC303.3@881.5,2942.52 867.72,2942.52 858.68,2951.55 858.68,2988.61 899.21,3029.13 C315.2@899.21,3031.1
  Bottom w12: v2@861.8,3117.7 861.8,3116.66 880.53,3097.94 885.53,3097.94 895.26,3088.21 895.26,3084.25 899.21,3080.3 C315.2@899.21,3031.1 ; R319.1@901.18,3084.25 R310.1@956.3,3084.25
REF_L_IN: P303.3 R311.2 | length 109
  Bottom w12: R311.2@822.44,3151.18 832.68,3161.42 P303.3@832.68,3255.91
REF_R: IC200.69 IC303.7 | length 1547.5
  Top w7.1: v2(723.94,2118.32) 740.85,2101.42 740.85,1753.98 879.19,1615.63 IC200.69@958.66,1615.63
  MID w8: v2(723.94,2118.32) 737.23,2131.61 737.23,2546.93 761.94,2571.64 761.94,2735.47 775.5,2749.02 775.5,2906.67 738.05,2944.12 v2(738.05,2953.66)
  Bottom w8: v2(738.05,2953.66) 746.6,2962.21 IC303.7@763.39,2962.21
REF_R_5V: C319.2 IC303.1 R309.1 R323.1 TVS303.1 | length 596.5
  Top w12: TVS303.1@769.29,2989.76 775.1,2995.58 798.8,2995.58 887.13,3083.91 v2(997.68,3083.91)
  Bottom w8: IC303.1@881.5,2981.89 913,2981.89 924.18,2970.7 975.67,2970.7 996.53,2991.56 996.53,2992.59 1033.07,3029.13 C319.2@1033.07,3031.1
  Bottom w12: v2(997.68,3083.91) R323.1@1034.69,3083.91 ; C319.2@1033.07,3031.1 1033.07,3082.28 R323.1@1034.69,3083.91 ; R309.1@1090.16,3084.25 R323.1@1035.04,3084.25 R323.1@1034.69,3083.91
REF_R_IN: P303.1 R309.2 | length 129.7
  Bottom w12: P303.1@1032.68,3255.91 1032.68,3225.91 1074.41,3184.17 1074.41,3164.96 1088.19,3151.18 R309.2@1090.16,3151.18
SD_DIR: IC200.56 P1.18 | length 993.9
  Top w7.1: v2(791.06,1866.46) 890.12,1866.46 936.15,1820.42 958.6,1820.42 IC200.56@958.66,1820.36
  Top w8: P1.18@358.94,1423.23 376.63,1423.23 405.06,1451.65 621.65,1451.65 712.06,1542.06 712.06,1865.46 v1(711.06,1866.46)
  Bottom w8: v1(711.06,1866.46) v2(791.06,1866.46)
SD_STP: IC200.57 P1.17 | length 1204.4
  Top w7.1: v2(791.06,1840.46) 897.59,1840.46 933.37,1804.67 IC200.57@958.66,1804.61 IC200.57@958.66,1804.61
  Top w8: P1.17@113.5,1423.23 130.63,1423.23 177.06,1469.65 612.17,1469.65 690.06,1547.53 v1(690.06,1840.46)
  Bottom w8: v1(690.06,1840.46) v2(791.06,1840.46)
SPI2_MISO: P1.28 P2.28 | length 1789.5
  Top w8: v2(1991.85,1972.62) P2.28@2041.24,1923.23
  Top w10: P1.28@358.94,1923.23 382.56,1923.23 462.56,2003.23 v2(527.94,2003.23)
  MID w10: v2(527.94,2003.23) 540.63,2003.23 554.02,2016.62 1025.33,2016.62 1033.94,2025.23 1065.94,2025.23 1074.55,2016.62 1275.55,2016.62 1288.94,2003.23 1683.24,2003.23 1741.24,1945.23 1851.49,1945.23 1878.89,1972.62 v2(1991.85,1972.62)
SPI2_MOSI: P1.29 P2.29 | length 1748.4
  Top w10: P1.29@113.5,2023.23 131,2023.23 169,2061.23 v2(527.94,2061.23) ; v2(1747.94,2066.23) 1790.94,2023.23 P2.29@1806.41,2023.23
  MID w10: v2(527.94,2061.23) 540.48,2061.23 548.48,2053.23 724.94,2053.23 753.94,2082.23 1731.94,2082.23 v2(1747.94,2066.23)
SPI2_nSCS: P1.24 P2.24 | length 1856.2
  Top w8: P1.24@358.94,1723.23 471.63,1723.23 v2(668.06,1919.65) ; v2(1989.94,1773.23) 2039.94,1723.23 P2.24@2051.85,1723.23
  MID w8: v2(668.06,1919.65) 668.06,1919.23 668.48,1919.65 1049.53,1919.65 1092.85,1876.33 1594.56,1876.33 1697.66,1773.23 v2(1989.94,1773.23)
SPI2_SCK: P1.27 P2.27 | length 1811.5
  Top w10: P1.27@113.5,1923.23 131,1923.23 172,1964.23 377.31,1964.23 446.31,2033.23 v2(529.03,2033.23) ; v2(1749.94,1966.23) 1792.94,1923.23 P2.27@1806.41,1923.23
  MID w10: v2(529.03,2033.23) 729.65,2033.23 731.65,2035.23 731.81,2035.07 762.96,2066.23 1649.94,2066.23 v2(1749.94,1966.23)
SPI_ADC_CSN: P2.30
SPI_ADC_MISO: P2.33
SPI_ADC_MOSI: P2.32
SPI_ADC_SCK: P2.31
SPI_MISO: IC200.9 IC201.2 P1.33 | length 2970
  Top w7.1: v2(1106.3,1399.45) IC200.9@1106.3,1483.74
  Top w8: IC201.2@339.01,415.94 393.1,415.94 v2(393.7,416.53)
  Top w10: P1.33@113.5,2223.23 127.24,2223.23 166.85,2183.62 v2(231.85,2183.62)
  MID w8: v2(231.85,2183.62) 308.55,2183.62 412.5,2079.66 412.5,2007.52 695.54,1724.48 695.54,1648.81 874.12,1470.23 1037.81,1470.23 1106.3,1401.73 v2(1106.3,1399.45)
  Bottom w8: v2(393.7,416.53) 507.87,530.71 507.87,1021.93 835.55,1349.61 1058.74,1349.61 1106.3,1397.17 v2(1106.3,1399.45)
SPI_MOSI: IC200.8 IC201.5 P1.32 | length 2621.2
  Top w7.1: IC201.5@553.58,315.94 557.58,319.94 583.62,319.94 625.06,361.37 625.06,758.65 873.06,1006.65 1008.23,1006.65 1094.49,1092.91 1094.49,1324.46 1080.3,1338.65 v2(1080.3,1399.45) 1080.3,1417.4 1090.55,1427.65 IC200.8@1090.55,1483.74
  Top w8: v2(358.94,2086.23) P1.32@358.94,2123.23
  MID w8: v2(358.94,2086.23) 358.94,2041.29 681.54,1718.68 681.54,1643.01 903.1,1421.45 1002.22,1421.45 1014.22,1433.45 1048.58,1433.45 1080.3,1401.73 v2(1080.3,1399.45)
SPI_nSCS: IC200.6 P1.30 | length 1096.3
  Top w7.1: v2(1028.3,1399.45) 1028.3,1404.99 1059.06,1435.75 IC200.6@1059.06,1483.74
  Top w8: v2(358.94,1985.23) P1.30@358.94,2023.23
  MID w8: v2(358.94,1985.23) 375.4,1985.23 653.54,1707.09 653.54,1631.41 891.5,1393.45 1013.81,1393.45 1019.81,1399.45 v2(1028.3,1399.45)
SPI_SCK: IC200.7 IC201.6 P1.31 | length 2737
  Top w7.1: IC201.6@553.58,365.94 576.34,365.94 604.06,393.65 604.06,765.94 864.77,1026.65 998.26,1026.65 1073.06,1101.45 1073.06,1317.61 1054.3,1336.37 v2(1054.3,1399.45) 1054.3,1411.19 1074.8,1431.7 IC200.7@1074.8,1483.74
  Top w10: P1.31@113.5,2123.23 132.24,2123.23 165.93,2089.54 230.93,2089.54 v2(231.85,2088.62)
  MID w8: v2(231.85,2088.62) 291.81,2088.62 667.54,1712.88 667.54,1637.21 897.3,1407.45 1008.02,1407.45 1020.02,1419.45 1036.58,1419.45 1054.3,1401.73 v2(1054.3,1399.45)
STATUS: IC200.12 P1.13 | length 1255.9
  Top w7.1: IC200.12@1153.54,1483.74 1153.54,1438.54 1183.46,1408.62 v2(1191.85,1408.62)
  Top w8: P1.13@113.5,1223.23 126.8,1223.23 175.22,1271.65 v2(179.06,1271.65)
  MID w8: v2(179.06,1271.65) 390.06,1271.65 496.06,1377.65 1169.16,1377.65 1191.85,1400.34 v2(1191.85,1408.62)
UART_RXD: IC200.10 P1.39 P200.3 | length 2359.7
  Top w7.1: IC200.10@1122.05,1483.74 1122.05,1411.99 1126.3,1407.73 1126.3,1405.45 v2(1132.3,1399.45) 1458.52,1073.23 P200.3@1606.41,1073.23
  Top w8: P1.39@113.5,2523.23 133.94,2523.23 174.94,2482.23 v2(174.94,2479.23)
  MID w8: v2(174.94,2479.23) 182.94,2479.23 358.06,2304.11 358.06,2154.85 426.5,2086.4 426.5,2013.32 709.54,1730.28 709.54,1654.61 879.92,1484.23 1049.81,1484.23 1132.3,1401.73 v2(1132.3,1399.45)
UART_TXD: IC200.11 P1.40 P200.2 | length 2197
  Top w7.1: IC200.11@1137.8,1483.74 1137.8,1422.24 1158.27,1401.76 v2@1161.85,1401.76 ; v2(1161.85,1398.62) v2@1161.85,1401.76 ; P200.2@1606.41,1173.23 1390.38,1173.23 v2@1161.85,1401.76
  Top w8: v2(358.94,2473.23) P1.40@358.94,2523.23
  MID w8: v2(358.94,2473.23) 372.06,2460.11 372.06,2160.65 440.5,2092.2 440.5,2019.12 723.54,1736.08 723.54,1660.41 885.72,1498.23 1061.81,1498.23 1161.41,1398.62 v2(1161.85,1398.62)
pads on no net: IC201.7 P1.14 P1.16 P1.25 P1.26 P1.34 P1.36 P1.38 P1.HOLE P2.8 P2.9 P2.10 P2.25 P2.HOLE P201.2 TVS300.6 TVS301.6 TVS302.6 TVS303.6 XTL200.1

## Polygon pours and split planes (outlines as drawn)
GND on MID "Top-No Net" (solid, pour order 13): 0,157.48 0,3188.98 cw(c157.48,3188.98) 157.48,3346.46 2007.87,3346.46 cw(c2007.88,3188.98) 2165.35,3188.98 2165.35,157.48 cw(c2007.87,157.48) 2007.87,0 157.48,0 cw(c157.48,157.48)
GND on Bottom "Top-No Net" (solid, pour order 4): 0,157.48 0,3188.98 cw(c157.48,3188.98) 157.48,3346.46 2007.87,3346.46 cw(c2007.88,3188.98) 2165.35,3188.98 2165.35,157.48 cw(c2007.87,157.48) 2007.87,0 157.48,0 cw(c157.48,157.48)
+3V3 on VM "+3V3_L04_P005" (solid, pour order 5): 0,157.48 0,3188.98 cw(c157.48,3188.98) 157.48,3346.46 2007.87,3346.46 cw(c2007.88,3188.98) 2165.35,3188.98 2165.35,157.48 cw(c2007.87,157.48) 2007.87,0 157.48,0 cw(c157.48,157.48)
GND on Top "Top-No Net" (solid, pour order 3): 0,157.48 0,3188.98 cw(c157.48,3188.98) 157.48,3346.46 2007.87,3346.46 cw(c2007.88,3188.98) 2165.35,3188.98 2165.35,157.48 cw(c2007.87,157.48) 2007.87,0 157.48,0 cw(c157.48,157.48)
+3V3 on Top "+3V3_L01_P008" (solid, pour order 0): 303.15,2889.76 295.28,2897.64 55.12,2897.64 39.37,2913.39 39.37,2956.69 55.12,2972.44 125.98,2972.44 125.98,3037 137.8,3048.82 228.35,3048.82 259.84,3080.31 259.84,3141.73 437.01,3141.73 452.76,3125.98 452.76,2940.95 405.51,2893.7 405.51,2787.4 389.76,2771.65 320.47,2771.65 303.15,2788.97
no net on Top Overlay "Top-No Net" (solid, pour order 2): 844.2,106.34 844.2,208 -0.8,208 -0.8,144.67 5.8,106.34
no net on Top Overlay "Top-No Net" (solid, pour order 1): 1321.15,106.34 1321.15,208 2166.15,208 2166.15,144.67 2159.55,106.34
GND on GND1 (split plane): 2018.25,3334.08 2028.58,3332.97 2038.8,3331.13 2048.86,3328.56 2058.71,3325.28 2068.31,3321.3 2077.59,3316.66 2086.52,3311.36 2095.05,3305.44 2103.14,3298.92 2110.74,3291.84 2117.82,3284.24 2124.33,3276.16 2130.25,3267.63 2135.55,3258.7 2140.2,3249.41 2144.18,3239.82 2147.45,3229.96 2150.02,3219.9 2151.87,3209.68 2152.98,3199.36 2153.33,3189.35 2153.3,3188.98 2153.3,3188.97 2153.3,157.48 2153.33,157.1 2152.98,147.1 2151.87,136.78 2150.02,126.56 2147.45,116.5 2144.17,106.64 2140.2,97.05 2135.55,87.76 2130.25,78.83 2124.33,70.3 2117.81,62.22 2110.74,54.62 2103.14,47.54 2095.05,41.02 2086.52,35.1 2077.59,29.8 2068.3,25.15 2058.71,21.18 2048.86,17.9 2038.79,15.33 2028.57,13.49 2018.25,12.38 2008.25,12.02 2007.87,12.06 157.48,12.06 157.1,12.02 147.1,12.38 136.78,13.49 126.56,15.33 116.49,17.9 106.64,21.18 97.05,25.15 87.76,29.8 78.83,35.1 70.3,41.02 62.22,47.54 54.61,54.62 47.54,62.22 41.02,70.3 35.1,78.83 29.8,87.76 25.15,97.05 21.18,106.64 17.9,116.5 15.33,126.56 13.49,136.78 12.38,147.1 12.02,157.1 12.06,157.48 12.06,3188.98 12.02,3189.35 12.38,3199.35 13.49,3209.68 15.33,3219.9 17.9,3229.96 21.18,3239.81 25.15,3249.41 29.8,3258.69 35.1,3267.63 41.02,3276.16 47.54,3284.24 54.61,3291.84 62.21,3298.92 70.3,3305.43 78.83,3311.36 87.76,3316.65 97.05,3321.3 106.64,3325.28 116.49,3328.56 126.56,3331.12 136.78,3332.97 147.1,3334.08 157.11,3334.44 157.48,3334.4 157.49,3334.4 2007.87,3334.4 2008.25,3334.44
GND on GND2 (split plane): 2018.25,3334.08 2028.58,3332.97 2038.8,3331.13 2048.86,3328.56 2058.71,3325.28 2068.31,3321.3 2077.59,3316.66 2086.52,3311.36 2095.05,3305.44 2103.14,3298.92 2110.74,3291.84 2117.82,3284.24 2124.33,3276.16 2130.25,3267.63 2135.55,3258.7 2140.2,3249.41 2144.18,3239.82 2147.45,3229.96 2150.02,3219.9 2151.87,3209.68 2152.98,3199.36 2153.33,3189.35 2153.3,3188.98 2153.3,3188.97 2153.3,157.48 2153.33,157.1 2152.98,147.1 2151.87,136.78 2150.02,126.56 2147.45,116.5 2144.17,106.64 2140.2,97.05 2135.55,87.76 2130.25,78.83 2124.33,70.3 2117.81,62.22 2110.74,54.62 2103.14,47.54 2095.05,41.02 2086.52,35.1 2077.59,29.8 2068.3,25.15 2058.71,21.18 2048.86,17.9 2038.79,15.33 2028.57,13.49 2018.25,12.38 2008.25,12.02 2007.87,12.06 157.48,12.06 157.1,12.02 147.1,12.38 136.78,13.49 126.56,15.33 116.49,17.9 106.64,21.18 97.05,25.15 87.76,29.8 78.83,35.1 70.3,41.02 62.22,47.54 54.61,54.62 47.54,62.22 41.02,70.3 35.1,78.83 29.8,87.76 25.15,97.05 21.18,106.64 17.9,116.5 15.33,126.56 13.49,136.78 12.38,147.1 12.02,157.1 12.06,157.48 12.06,3188.98 12.02,3189.35 12.38,3199.35 13.49,3209.68 15.33,3219.9 17.9,3229.96 21.18,3239.81 25.15,3249.41 29.8,3258.69 35.1,3267.63 41.02,3276.16 47.54,3284.24 54.61,3291.84 62.21,3298.92 70.3,3305.43 78.83,3311.36 87.76,3316.65 97.05,3321.3 106.64,3325.28 116.49,3328.56 126.56,3331.12 136.78,3332.97 147.1,3334.08 157.11,3334.44 157.48,3334.4 157.49,3334.4 2007.87,3334.4 2008.25,3334.44

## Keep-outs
Keep-Out Layer:
  the board outline again, w1

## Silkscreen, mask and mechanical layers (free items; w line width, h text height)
Top Overlay:
  lines w11.81: 712.6,1013.98 1358.27,1013.98 1358.27,2427.65 712.6,2427.65 712.6,1013.98
  text "GND" at 715.18,3192.52 h35 r270
  text "REF_L" at 815.18,3192.52 h35 r270
  text "REF_H" at 915.18,3192.52 h35 r270
  text "REF_R" at 1015.18,3192.52 h35 r270
  text "GND" at 1215.18,3192.52 h35 r270
  text "HALL_UX" at 1315.18,3192.52 h35 r270
  text "HALL_V" at 1415.18,3192.52 h35 r270
  text "HALL_WY" at 1515.18,3192.52 h35 r270
  text "+5V" at 615.18,3192.13 h35 r270
  text "+5V" at 1115.18,3192.13 h35 r270
  text "GND" at 715.68,2782.17 h35 r270
  text "ENC2_A" at 815.68,2782.17 h35 r270
  text "ENC2_B" at 915.68,2782.17 h35 r270
  text "ENC2_N" at 1015.68,2782.17 h35 r270
  text "+5V" at 1115.18,2782.17 h35 r270
  text "GND" at 1215.18,2782.17 h35 r270
  text "ENC1_A" at 1315.68,2782.17 h35 r270
  text "ENC1_B" at 1415.68,2782.17 h35 r270
  text "ENC1_N" at 1515.68,2782.17 h35 r270
  text "+5V" at 615.68,2781.78 h35 r270
  text "PWM" at 408.94,1655.91 h31.5
  text "GND" at 408.94,1559.06 h31.5
  text "GND" at 1665.86,1257.49 h31.5
  text "TXD" at 1665.86,1157.49 h31.5
  text "RXD" at 1665.86,1057.49 h31.5
  text "RTM" at 854.33,1034.64 h40
  text "UART" at 1539.37,959.05 h40
  text "GND" at 698.42,374.96 h31.5 r90
  text "AGPI_A" at 798.42,374.96 h31.5 r90
  text "GND" at 898.42,374.96 h31.5 r90
  text "AGPI_B" at 998.42,374.96 h31.5 r90
  text "+5V" at 1198.42,374.96 h31.5 r90
  text "GND" at 1298.42,374.96 h31.5 r90
  text "AENC_UX" at 1398.42,374.96 h31.5 r90
  text "AENC_VN" at 1498.42,374.97 h31.5 r90
  text "AENC_WY" at 1598.42,374.96 h31.5 r90
  text "GND" at 1698.42,374.96 h31.5 r90
  text "BRAKE" at 1798.42,374.96 h31.5 r90
  text "'.BoardName'" at 295.28,51.87 h40.15
  text "v'.BoardVersion'" at 1730.23,51.87 h40.15
Bottom Overlay:
  drawing of 35 lines, arcs and shapes, not listed
  text "www.TRINAMIC.com" at 1635.68,1355.46 h65
  text "TMC-Evaluation-Platform:" at 1536.34,1276.84 h40.15
  text "'.BoardName'" at 1496.97,1182.36 h53.54
  text "Interfaces:" at 1536.34,1115.43 h40.15
  text "'.Interfaces'" at 1496.97,1036.69 h53.54
  text "v'.BoardVersion'" at 1588.94,453.23 h66.93
  text "+3V3" at 414.06,255.91 h30 r30
  text "GPIO0" at 535.23,158.92 h23.62 r30
  text "GPIO1" at 630.77,158.92 h23.62 r30
  text "GPIO2" at 726.31,158.92 h23.62 r30
  text "DBG_SPI_nSCS" at 821.85,158.92 h23.62 r30
  text "DBG_SPI_SCK" at 917.38,158.92 h23.62 r30
  text "DBG_SPI_TRG" at 1012.92,158.92 h23.62 r30
  text "DBG_SPI_MISO" at 1108.46,158.92 h23.62 r30
  text "DBG_SPI_TRG" at 1204,158.92 h23.62 r30
  text "AENC_UX_INN" at 1299.54,158.92 h23.62 r30
  text "AENC_VN_INN" at 1395.07,158.92 h23.62 r30
  text "AENC_WY_INN" at 1490.61,158.92 h23.62 r30
  text "ADC_I1_INN" at 1586.15,158.92 h23.62 r30
  text "ADC_I0_INN" at 1681.69,158.92 h23.62 r30
  text "+5V" at 445.05,149.98 h30 r30
  text "GND" at 1782.58,149.98 h30 r30

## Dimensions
157.48,0 to 157.48,3346.46 on Dimension
2165.35,157.48 to 0,157.48 on Dimension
